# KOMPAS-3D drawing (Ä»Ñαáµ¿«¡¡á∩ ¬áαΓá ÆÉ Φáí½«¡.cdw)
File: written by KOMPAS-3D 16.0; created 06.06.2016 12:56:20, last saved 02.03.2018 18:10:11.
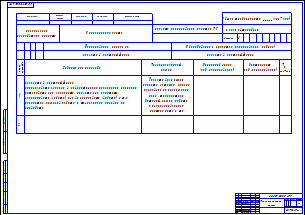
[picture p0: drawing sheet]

Sheet 1: A1, landscape

Title block, sheet 1: name: Технологическая / карта; designation: ДП 009.00.00 4ТЧ; scale: 1:1; sheets: 1; organisation: САТК-47гр.; sheet format: A1; revision letter: Д; stored path: C:\Documents and Settings\Admin\Мои документы\Мои рисунки\Базылев опер ката.cdw; drawn by: Ковалёв Р.С.; checked by: Ершов М.В.; standards control: Бервинова Н.К.; approved by: Ященко М.К.

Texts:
  Базылев опер карта
  satk
  Normal
  heading 1
Dimensions and other numbers on the sheet: 1:1; 1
